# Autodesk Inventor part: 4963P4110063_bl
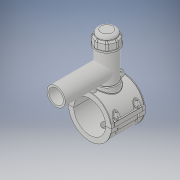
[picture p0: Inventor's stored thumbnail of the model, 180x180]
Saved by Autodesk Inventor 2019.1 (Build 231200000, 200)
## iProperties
Created: 2017-07
Part Number: 4963P4110063_bl
Material: Generic
Document SubType Name: Modeling
Designer: KIM
Density: 1 g/cm^3
Appearance: Default
Author: KIM
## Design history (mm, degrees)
derived "4963P4.ipt"
feature "Solid1::4963P4.ipt" dims "ScaleForDerivedMember" = 10
feature "Solid2::4963P4.ipt" dims "ScaleForDerivedMember" = 10
feature "Solid3::4963P4.ipt" dims "ScaleForDerivedMember" = 10
tag "TaggingFeature1"
body "Solid1"
body "Solid2"
body "Solid3"
other parameters: "d2" = 148 [user parameter], "d3" = 27.5 [user parameter], "d4" = 118 [user parameter], "d5" = 0 [user parameter], "d6" = 0.1 [user parameter], "d8" = 0 [user parameter], "d19" = 6 [user parameter], "d20" = 6 [user parameter], "d21" = 70.8 [user parameter], "d23" = 0 [user parameter], "d24" = 35.4 [user parameter], "d26" = 0 [user parameter], "d27" = 3 [user parameter], "d28" = 3 [user parameter], "d29" = 3 [user parameter], "d30" = 36.66667 [user parameter], "d31" = 6 [user parameter], "d32" = 0 [user parameter], "d33" = 0 [user parameter], "d34" = 0.6 [user parameter], "d40" = 74.36 [user parameter], "d41" = 77 [user parameter], "d43" = 0 [user parameter], "d45" = 0 [user parameter], "d47" = 142.3 [user parameter], "d70" = 15 [user parameter], "d72" = 0 [user parameter], "d73" = 6 [user parameter], "d75" = 5 [user parameter], "d76" = 0 [user parameter], "d77" = 5.5 [user parameter], "d78" = 85 [user parameter], "d79" = 15 [user parameter], "d80" = 47.2 [user parameter], "d82" = 5 deg [user parameter], "d84" = 4 [user parameter], "d85" = 14 [user parameter], "d86" = 0 [user parameter], "d87" = 3 [user parameter], "d88" = 0 [user parameter], "d89" = 1 [user parameter], "d90" = 1 [user parameter], "d91" = 94.4 [user parameter], "d92" = 0 [user parameter], "d93" = 0.5 [user parameter], "d94" = 57.89474 [user parameter], "d96" = 145.86 [user parameter], "d97" = 2.36 [user parameter], "d98" = 0 [user parameter], "d102" = 1.1 [user parameter], "d120" = 140 deg [user parameter], "d121" = 24.228 [user parameter], "d122" = 20 deg [user parameter], "d123" = 286 [user parameter], "d124" = 85.8 [user parameter], "d126" = 0 [user parameter], "d143" = 113.3 [user parameter], "d145" = 25.38462 [user parameter], "d149" = 1.65 [user parameter], "d150" = 27.92308 [user parameter], "d153" = 118 [user parameter], "d154" = 0 [user parameter], "d156" = 71.5 [user parameter], "d157" = 160 deg [user parameter], "d159" = 6.6 [user parameter], "d161" = 1.65 [user parameter], "d162" = 70.8 [user parameter], "d163" = 0 [user parameter], "d164" = 55 [user parameter], "d167" = 11 [user parameter], "d168" = 69.7561 [user parameter], "d170" = 3.75 [user parameter], "d172" = 0 [user parameter], "d173" = 1 [user parameter], "d175" = 55 [user parameter], "d176" = 20 deg [user parameter], "d177" = 7.7 [user parameter], "d178" = 33 [user parameter], "d180" = 0 [user parameter], "d183" = 13.2 [user parameter], "d184" = 6.16 [user parameter], "d185" = 38.35 [user parameter], "d186" = 38.35 [user parameter], "d187" = 71.5 [user parameter], "d188" = 9.9 [user parameter], "d189" = 7.7 [user parameter], "d190" = 0 [user parameter], "d191" = 107.25 [user parameter], "d193" = 8 [user parameter], "d194" = 4.13 [user parameter], "d195" = 90 deg [user parameter], "d197" = 0 [user parameter], "d199" = 0 [user parameter], "d200" = 16.5 [user parameter], "d202" = 0 [user parameter], "d203" = 177 [user parameter], "d204" = 73.15 [user parameter], "d205" = 53.9 [user parameter], "d206" = 65.45 [user parameter], "d207" = 132.75 [user parameter], "d208" = 138.06 [user parameter], "d209" = 164.61 [user parameter], "d210" = 66.22 [user parameter], "d211" = 77 [user parameter], "d212" = 61.6 [user parameter], "d213" = 29.25 [user parameter], "d216" = 0 [user parameter], "d217" = 11 [user parameter], "d218" = 11 [user parameter], "d219" = 2.2 [user parameter], "d224" = 0 [user parameter], "d225" = 64 [user parameter], "d226" = 63 [user parameter], "d227" = 50.4 [user parameter], "d228" = 175 [user parameter], "d230" = 6.6 [user parameter], "B_" = 148 [user parameter], "L_" = 118 [user parameter], "d_t" = 6 [user parameter], "H_2" = 177 [user parameter]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
